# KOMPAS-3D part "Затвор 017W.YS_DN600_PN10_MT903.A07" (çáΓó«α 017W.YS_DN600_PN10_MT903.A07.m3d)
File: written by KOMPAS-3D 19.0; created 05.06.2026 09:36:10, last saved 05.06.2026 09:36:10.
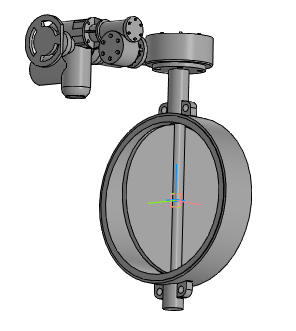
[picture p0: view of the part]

Document properties: Автор: Энергия; Полное имя файла: ..\..\..\3d для проектировщиков\x.x Тип 017W.Y(S) Затвор дисковый поворотный межфланцевый\Затвор 017W.Y(S)_DN32-DN1200_QT.A_MT903.A\Затвор 017W.YS_DN600_PN10_MT903.A07.a3d

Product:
- Part/product: Затвор 017W.YS_DN600_PN10_MT903.A07
    Масса: 296.631

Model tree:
1. Операция без истории:1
